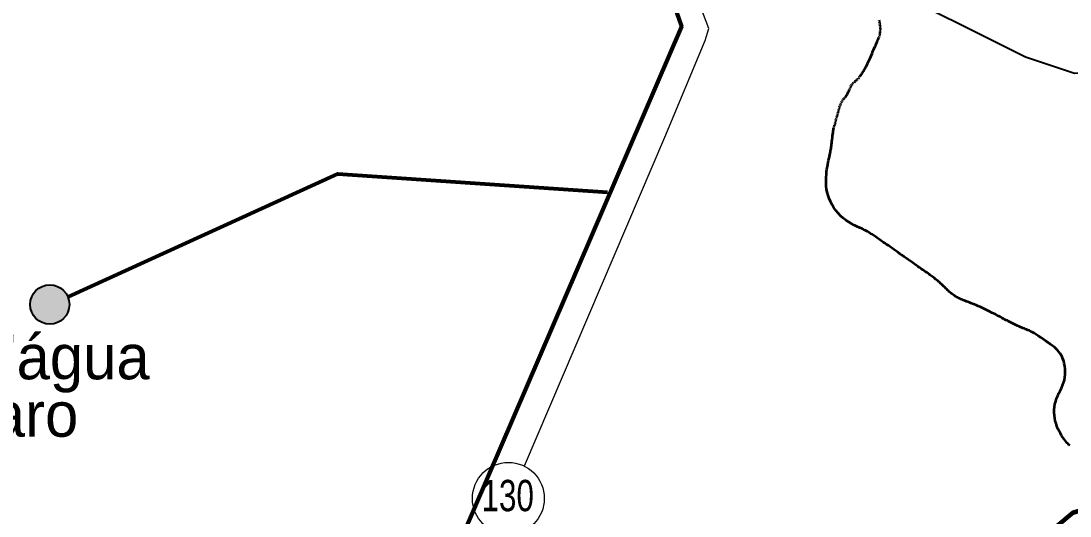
# Model space of a CAD drawing. Extents: x 553962 to 842807, y 8883888 to 9032388.
# Drawn here: x 685616 to 697335, y 8956017 to 8961546 of the extents above; entities that cross this region are included whole.
import ezdxf
from ezdxf.enums import TextEntityAlignment as Align

# ---------------------------------------------------------------- set-up
doc = ezdxf.new("R2010")
doc.units = 0
doc.header["$LTSCALE"] = 200
for name, color, linetype, lineweight in [('12', 7, 'Continuous', 25), ('24', 7, 'Continuous', 25), ('28', 7, 'Continuous', 40), ('41', 7, 'Continuous', 40), ('48', 7, 'Continuous', 25), ('9', 7, 'Continuous', 90)]:
    doc.layers.add(name, color=color, linetype=linetype, lineweight=lineweight)

msp = doc.modelspace()

# ---------------------------------------------------------------- hatches: boundary and pattern name
at = {"layer": '41'}
msp.add_hatch(color=256, dxfattribs=at).paths.add_polyline_path([(686156.7, 8958379.6, 1), (685719.1, 8958379.6, 1)])

# ---------------------------------------------------------------- linework, layer by layer
at = {"layer": '12'}
msp.add_lwpolyline([(691240.8, 8956578.2), (692809.2, 8960246.9), (693257.6, 8961326.5), (693299.9, 8961463.3), (692951.1, 8962385.1), (692776, 8962756.9), (692786.9, 8963010.2)], dxfattribs=at)
at = {"layer": '12', "lineweight": 40}
msp.add_lwpolyline([(693487.4, 8962819.8), (696836.9, 8961144.8), (697384.1, 8960961.8), (697603.7, 8960973.6), (697714.4, 8961082.3), (698321.2, 8961447.4), (698679, 8961567.8), (700187.3, 8961472.5), (701093.5, 8961547), (704410.2, 8961560.7)], dxfattribs=at)
at = {"layer": '24', "lineweight": 53}
for p, q in [((695206.1, 8961545.2), (695204, 8961554.7)), ((695210, 8961525.8), (695208.1, 8961535.5)), ((695213.1, 8961506.8), (695211.6, 8961516.2)), ((695215.1, 8961489), (695214.2, 8961497.7)), ((695216.2, 8961472.6), (695215.8, 8961480.6)), ((695216.2, 8961443), (695216.4, 8961450.1)), ((695216.5, 8961457.4), (695216.5, 8961464.9)), ((695203.7, 8961369.9), (695206.5, 8961378.2)), ((695208.8, 8961386.1), (695210.8, 8961393.7)), ((695212.3, 8961401), (695213.5, 8961408.2)), ((695214.3, 8961415.2), (695215, 8961422.2)), ((695215.5, 8961429.1), (695215.9, 8961436)), ((694912.2, 8960850.5), (694917.1, 8960855.5)), ((694922.1, 8960860.3), (694927, 8960865)), ((694932, 8960869.5), (694936.8, 8960873.7)), ((694941.4, 8960877.7), (694945.8, 8960881.5)), ((694950, 8960885.1), (694954.1, 8960888.7)), ((694958.2, 8960892.6), (694962.4, 8960896.8)), ((694966.8, 8960901.5), (694971.5, 8960906.9)), ((694976.7, 8960913), (694982.2, 8960920.1)), ((694874.5, 8960788.4), (694878.1, 8960796.7)), ((694881.6, 8960804.2), (694885, 8960811.2)), ((694888.3, 8960817.6), (694891.8, 8960823.7)), ((694895.4, 8960829.4), (694899.2, 8960834.8)), ((694903.2, 8960840.2), (694907.6, 8960845.4)), ((694773.6, 8960621), (694777.4, 8960629.7)), ((694781.6, 8960638.2), (694786, 8960646.3)), ((694790.9, 8960654), (694796.2, 8960661.2)), ((694801.8, 8960668.2), (694807.6, 8960674.9)), ((694813.6, 8960681.6), (694819.7, 8960688.5)), ((694738.8, 8960501.8), (694741.3, 8960509.7)), ((694743.7, 8960517.7), (694745.9, 8960525.8)), ((694748.1, 8960534), (694750.2, 8960542.3)), ((694752.2, 8960550.6), (694754.3, 8960559.1)), ((694756.5, 8960567.7), (694758.9, 8960576.3)), ((694761.3, 8960585.2), (694764, 8960594.1)), ((694767, 8960603.1), (694770.2, 8960612.1)), ((694707.7, 8960391.1), (694709.7, 8960398.4)), ((694711.6, 8960406), (694713.5, 8960413.8)), ((694715.5, 8960421.7), (694717.4, 8960429.8)), ((694719.5, 8960437.8), (694721.6, 8960446)), ((694723.8, 8960454.1), (694726.2, 8960462.1)), ((694728.6, 8960470), (694731.2, 8960478)), ((694733.8, 8960485.9), (694736.3, 8960493.8)), ((694699.2, 8960361.1), (694701.4, 8960369.2)), ((694703.5, 8960376.8), (694705.6, 8960383.9))]:
    msp.add_line(p, q, dxfattribs=at)
at = {"layer": '24'}
for p, q in [((695206.1, 8961545.2), (695208.1, 8961535.5)), ((695210, 8961525.8), (695211.6, 8961516.2)), ((695213.1, 8961506.8), (695214.2, 8961497.7)), ((695215.1, 8961489), (695215.8, 8961480.6)), ((695216.2, 8961443), (695215.9, 8961436)), ((695216.2, 8961472.6), (695216.5, 8961464.9)), ((695216.5, 8961457.4), (695216.4, 8961450.1)), ((695203.7, 8961369.9), (695200.3, 8961361)), ((695208.8, 8961386.1), (695206.5, 8961378.2)), ((695212.3, 8961401), (695210.8, 8961393.7)), ((695214.3, 8961415.2), (695213.5, 8961408.2)), ((695215.5, 8961429.1), (695215, 8961422.2)), ((694922.1, 8960860.3), (694917.1, 8960855.5)), ((694932, 8960869.5), (694927, 8960865)), ((694941.4, 8960877.7), (694936.8, 8960873.7)), ((694950, 8960885.1), (694945.8, 8960881.5)), ((694958.2, 8960892.6), (694954.1, 8960888.7)), ((694966.8, 8960901.5), (694962.4, 8960896.8)), ((694976.7, 8960913), (694971.5, 8960906.9)), ((694988.2, 8960928.1), (694982.2, 8960920.1)), ((694874.5, 8960788.4), (694870.7, 8960779.5)), ((694881.6, 8960804.2), (694878.1, 8960796.7)), ((694888.3, 8960817.6), (694885, 8960811.2)), ((694895.4, 8960829.4), (694891.8, 8960823.7)), ((694903.2, 8960840.2), (694899.2, 8960834.8)), ((694912.2, 8960850.5), (694907.6, 8960845.4)), ((694773.6, 8960621), (694770.2, 8960612.1)), ((694781.6, 8960638.2), (694777.4, 8960629.7)), ((694790.9, 8960654), (694786, 8960646.3)), ((694801.8, 8960668.2), (694796.2, 8960661.2)), ((694813.6, 8960681.6), (694807.6, 8960674.9)), ((694825.8, 8960695.7), (694819.7, 8960688.5)), ((694738.8, 8960501.8), (694736.3, 8960493.8)), ((694743.7, 8960517.7), (694741.3, 8960509.7)), ((694748.1, 8960534), (694745.9, 8960525.8)), ((694752.2, 8960550.6), (694750.2, 8960542.3)), ((694756.5, 8960567.7), (694754.3, 8960559.1)), ((694761.3, 8960585.2), (694758.9, 8960576.3)), ((694767, 8960603.1), (694764, 8960594.1)), ((694707.7, 8960391.1), (694705.6, 8960383.9)), ((694711.6, 8960406), (694709.7, 8960398.4)), ((694715.5, 8960421.7), (694713.5, 8960413.8)), ((694719.5, 8960437.8), (694717.4, 8960429.8)), ((694723.8, 8960454.1), (694721.6, 8960446)), ((694728.6, 8960470), (694726.2, 8960462.1)), ((694733.8, 8960485.9), (694731.2, 8960478)), ((694699.2, 8960361.1), (694696.9, 8960351.9)), ((694703.5, 8960376.8), (694701.4, 8960369.2))]:
    msp.add_line(p, q, dxfattribs=at)
at = {"layer": '24', "lineweight": 53}
for points in [[(694988.2, 8960928.1), (694994.5, 8960936.7), (695001, 8960945.8), (695007.6, 8960955.3), (695014.2, 8960965), (695020.7, 8960974.9), (695027, 8960984.7), (695033.1, 8960994.3), (695039.1, 8961004.1), (695045.1, 8961014.5), (695051.4, 8961025.8), (695057.9, 8961038.3), (695065, 8961052.5), (695072.8, 8961068.8), (695081.4, 8961087.4), (695091, 8961108.7), (695101.2, 8961132), (695112, 8961156.7), (695123, 8961182.2), (695134, 8961207.7), (695144.6, 8961232.5), (695154.7, 8961256.1), (695164, 8961277.6), (695172.3, 8961296.5), (695179.6, 8961313), (695186, 8961327.5), (695191.5, 8961340.1), (695196.2, 8961351.1), (695200.3, 8961361)], [(694825.8, 8960695.7), (694831.7, 8960703.3), (694837.5, 8960711.5), (694843, 8960720.4), (694848.2, 8960730), (694853.2, 8960739.8), (694858, 8960749.9), (694862.5, 8960760), (694866.7, 8960769.9), (694870.7, 8960779.5)], [(694610.5, 8959801.8), (694612.9, 8959833), (694616.2, 8959863.1), (694620.1, 8959891.9), (694624.3, 8959919.5), (694628.9, 8959945.6), (694633.6, 8959970.2), (694638.3, 8959993.2), (694642.9, 8960014.6), (694647.3, 8960034.3), (694651.3, 8960052.2), (694654.8, 8960068.3), (694657.9, 8960082.9), (694660.6, 8960096.7), (694663.1, 8960109.9), (694665.3, 8960123.1), (694667.5, 8960136.7), (694669.5, 8960151.2), (694671.6, 8960167.1), (694673.7, 8960184.6), (694675.9, 8960203.4), (694678.2, 8960223), (694680.5, 8960243), (694682.8, 8960262.7), (694685.2, 8960281.7), (694687.6, 8960299.4), (694689.9, 8960315.5), (694692.3, 8960329.4), (694694.6, 8960341.5), (694696.9, 8960351.9)], [(695412.6, 8958963.5), (695390.1, 8958979.4), (695368.3, 8958994.5), (695347.1, 8959009), (695326.3, 8959023.1), (695305.9, 8959036.8), (695285.8, 8959050.4), (695265.9, 8959063.9), (695246.1, 8959077.5), (695226.2, 8959091.4), (695206.1, 8959105.7), (695185.8, 8959120.3), (695164.8, 8959135.2), (695143.1, 8959150.1), (695120.4, 8959165), (695096.6, 8959179.9), (695071.3, 8959194.5), (695044.4, 8959208.8), (695015.8, 8959222.9), (694985.9, 8959236.9), (694954.9, 8959251.4), (694923.4, 8959266.7), (694891.7, 8959283.3), (694860.2, 8959301.5), (694829.4, 8959321.8), (694799.7, 8959344.6), (694771.4, 8959370.2), (694744.8, 8959398.3), (694720.1, 8959428.6), (694697.5, 8959460.6), (694677.2, 8959494), (694659.3, 8959528.4), (694644.1, 8959563.4), (694631.8, 8959598.6), (694622.4, 8959633.7), (694615.8, 8959668.4), (694611.6, 8959702.8), (694609.5, 8959736.5), (694609.3, 8959769.6), (694610.5, 8959801.8)], [(695976.9, 8958531), (695967.2, 8958540.1), (695957.7, 8958549.4), (695948.1, 8958558.9), (695938.5, 8958568.5), (695928.9, 8958578.1), (695919.2, 8958587.8), (695909.4, 8958597.3), (695899.5, 8958606.6), (695889.5, 8958615.8), (695879.4, 8958624.8), (695869.1, 8958633.6), (695858.8, 8958642.3), (695848.4, 8958650.8), (695837.9, 8958659.2), (695827.4, 8958667.5), (695816.9, 8958675.7), (695806.4, 8958683.8), (695795.7, 8958692), (695784.8, 8958700.2), (695773.5, 8958708.6), (695761.6, 8958717.3), (695749.1, 8958726.3), (695735.9, 8958735.7), (695721.7, 8958745.6), (695706.5, 8958756), (695690.3, 8958767), (695673.1, 8958778.7), (695655, 8958791), (695636, 8958803.9), (695616.2, 8958817.6), (695595.5, 8958832), (695574, 8958847.1), (695551.8, 8958862.9), (695529, 8958879.4), (695505.8, 8958896.2), (695482.3, 8958913.2), (695458.9, 8958930.2), (695435.6, 8958947.1), (695412.6, 8958963.5)], [(696565.6, 8958234), (696553, 8958240.7), (696540.1, 8958247.5), (696526.7, 8958254.6), (696512.5, 8958262), (696497.3, 8958269.9), (696480.9, 8958278.4), (696462.9, 8958287.6), (696443.2, 8958297.7), (696422.1, 8958308.3), (696399.9, 8958319.3), (696377.1, 8958330.5), (696354, 8958341.7), (696331, 8958352.5), (696308.5, 8958362.8), (696286.8, 8958372.3), (696266.3, 8958381), (696247, 8958388.7), (696228.8, 8958395.7), (696211.6, 8958402.1), (696195.3, 8958408), (696179.9, 8958413.6), (696165.2, 8958418.8), (696151.3, 8958424), (696138, 8958429.1), (696125.3, 8958434.3), (696113, 8958439.6), (696101.2, 8958445), (696089.8, 8958450.5), (696078.8, 8958456.3), (696067.9, 8958462.3), (696057.3, 8958468.6), (696046.9, 8958475.3), (696036.5, 8958482.3), (696026.3, 8958489.6), (696016.2, 8958497.3), (696006.3, 8958505.3), (695996.4, 8958513.5), (695986.6, 8958522.1), (695976.9, 8958531)], [(697236.7, 8957815.1), (697224.9, 8957833.8), (697211.5, 8957851.4), (697196.4, 8957868.2), (697179.4, 8957884.7), (697160.2, 8957901.4), (697138.7, 8957918.7), (697114.9, 8957936.9), (697089.2, 8957955.7), (697062.3, 8957974.8), (697034.9, 8957993.6), (697007.6, 8958011.9), (696981, 8958029.1), (696955.8, 8958044.8), (696932.7, 8958058.6), (696912.1, 8958070.2), (696893.7, 8958079.8), (696877.2, 8958087.9), (696862.2, 8958094.6), (696848.2, 8958100.5), (696834.9, 8958105.8), (696821.7, 8958110.9), (696808.4, 8958116.1), (696794.5, 8958121.7), (696780.1, 8958127.8), (696765.2, 8958134.2), (696750.2, 8958141), (696734.9, 8958148), (696719.6, 8958155.2), (696704.3, 8958162.5), (696689.2, 8958169.8), (696674.4, 8958177.2), (696659.8, 8958184.6), (696645.5, 8958191.9), (696631.5, 8958199.1), (696617.8, 8958206.3), (696604.3, 8958213.4), (696591.2, 8958220.4), (696578.3, 8958227.2), (696565.6, 8958234)], [(697331.3, 8956805.9), (697323.2, 8956813.3), (697314.3, 8956822.1), (697304.5, 8956832.4), (697293.7, 8956844.7), (697281.9, 8956859.2), (697269, 8956876.1), (697255.3, 8956895.4), (697241.2, 8956916.7), (697227.2, 8956940), (697213.5, 8956965.1), (697200.6, 8956991.7), (697188.9, 8957019.6), (697178.8, 8957048.7), (697170.6, 8957078.7), (697164.4, 8957109.5), (697160.3, 8957140.9), (697158.5, 8957172.5), (697159, 8957204.3), (697161.8, 8957236), (697167.1, 8957267.4), (697175, 8957298.3), (697185.4, 8957328.5), (697197.7, 8957358.2), (697211.2, 8957387.5), (697225.2, 8957416.7), (697239.1, 8957446), (697252, 8957475.4), (697263.2, 8957505.3), (697272.1, 8957535.8), (697278.2, 8957567), (697281.4, 8957598.5), (697282.1, 8957630), (697280.5, 8957661.1), (697276.8, 8957691.2), (697271.4, 8957720), (697264.5, 8957747.1), (697256.3, 8957772.1), (697247.1, 8957794.6), (697236.7, 8957815.1)]]:
    msp.add_lwpolyline(points, dxfattribs=at)
at = {"layer": '28', "lineweight": 80}
for points in [[(692531.7, 8962810.1), (692994.2, 8961483.6), (686929, 8947387.5), (686925.3, 8947370.5)], [(686144.4, 8958465.4), (689156.4, 8959838.1), (692167.8, 8959633.8)]]:
    msp.add_lwpolyline(points, dxfattribs=at)
at = {"layer": '41'}
msp.add_circle((685937.9, 8958379.6), 218.8, dxfattribs=at)
at = {"layer": '48'}
msp.add_circle((691061.1, 8956214.5), 401.3, dxfattribs=at)
at = {"layer": '9'}
msp.add_lwpolyline([(691582, 8951218.7), (697371.2, 8956056), (705081.2, 8958366.8), (713138.6, 8969695)], dxfattribs=at)
for points in [[(637260.6, 8972975.8), (641524.5, 8971056.2), (652526.1, 8965412.7), (653164.3, 8965062.8), (670790.5, 8953770.1), (686194, 8943929.9), (696283.3, 8937647.1)], [(694874, 8947402.7), (694491.4, 8947729), (693981.6, 8948105.1), (692654.2, 8949437.3), (691811.8, 8950292), (691552.9, 8951277.6), (691093.4, 8951755.3), (689976, 8951721.8), (689441.2, 8951996.3), (689158.9, 8952576.6), (688699.5, 8953029), (687605.5, 8953400.8), (685873.4, 8954400.8), (684752.3, 8955101.5), (681638, 8958243.7), (680641.1, 8959527.7), (679425.4, 8960995.9)]]:
    msp.add_spline(points, degree=3, dxfattribs=at)

# ---------------------------------------------------------------- texts
at = {"layer": '41'}
for s, p in [("Olho D'água", (683358.1, 8957544.4)), ('do Amaro', (683358.1, 8956902.6))]:
    msp.add_text(s, height=500, dxfattribs=at).set_placement(p)
at = {"layer": '48', "width": 0.75}
msp.add_text('130', height=350, dxfattribs=at).set_placement((691053.4, 8956071), align=Align.CENTER)

doc.saveas('drawing.dxf')
